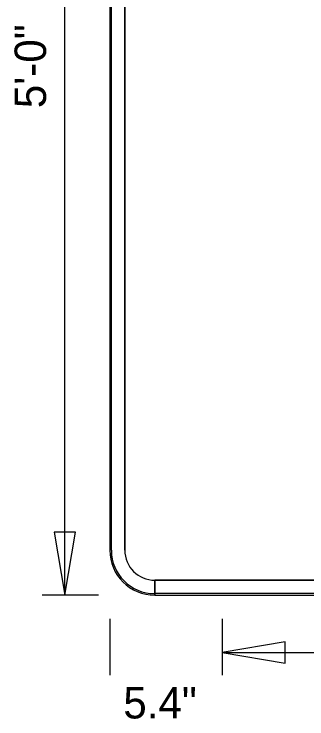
# Model space of a CAD drawing. Extents: x 0 to 770, y 0 to 495.
# Drawn here: x 610.7 to 643.3, y 9.2 to 87.5 of the extents above; entities that cross this region are included whole.
import ezdxf

# ---------------------------------------------------------------- set-up
doc = ezdxf.new("R2010")
doc.units = 0
for name, color, linetype in [('Dimension', 7, 'Continuous'), ('GSBWFill', 7, 'Continuous'), ('GSColorFill', 7, 'Continuous'), ('GSDims', 7, 'Continuous'), ('GSOutline', 7, 'Continuous')]:
    doc.layers.add(name, color=color, linetype=linetype)

msp = doc.modelspace()

# ---------------------------------------------------------------- linework, layer by layer
at = {"layer": 'Dimension'}
for points in [[(616.382, 22.923), (617.571, 29.939), (615.193, 29.939)], [(633.863, 16.542), (640.88, 15.354), (640.88, 17.731)]]:
    msp.add_lwpolyline(points, close=True, dxfattribs=at)
at = {"layer": 'GSBWFill'}
for p, q in [((621.395, 137.635), (621.395, 27.91)), ((623.057, 27.91), (623.057, 137.635)), ((626.382, 22.923), (626.382, 24.585)), ((716.157, 24.585), (626.399, 24.585)), ((626.399, 24.585), (626.399, 22.923)), ((626.399, 22.923), (716.157, 22.923))]:
    msp.add_line(p, q, dxfattribs=at)
for radius in [4.988, 3.325]:
    msp.add_arc((626.382, 27.91), radius, 180, 270, dxfattribs=at)
at = {"layer": 'GSColorFill'}
for p, q in [((621.395, 137.635), (621.395, 27.91)), ((621.395, 137.635), (621.395, 27.91)), ((621.395, 137.635), (621.395, 27.91)), ((621.561, 27.91), (621.561, 137.635)), ((623.057, 27.91), (623.057, 137.635)), ((626.382, 22.923), (626.382, 24.585)), ((716.157, 24.585), (626.399, 24.585)), ((626.399, 24.585), (626.399, 22.923)), ((626.382, 22.923), (626.382, 23.089)), ((626.382, 22.923), (716.157, 22.923)), ((716.157, 23.089), (626.384, 23.089)), ((626.384, 23.089), (626.384, 22.923)), ((626.384, 22.923), (716.157, 22.923)), ((626.399, 22.923), (716.157, 22.923))]:
    msp.add_line(p, q, dxfattribs=at)
for radius in [4.988, 4.988, 4.988, 4.821, 3.325]:
    msp.add_arc((626.382, 27.91), radius, 180, 270, dxfattribs=at)
at = {"layer": 'GSDims'}
for p, q in [((616.382, 22.923), (616.382, 142.623)), ((620.132, 22.923), (613.882, 22.923)), ((621.395, 20.292), (621.395, 14.042)), ((633.863, 20.292), (633.863, 14.042)), ((633.863, 20.292), (633.863, 14.042)), ((633.863, 16.542), (707.097, 16.542))]:
    msp.add_line(p, q, dxfattribs=at)
at = {"layer": 'GSOutline'}
for p, q in [((621.395, 137.635), (621.395, 27.91)), ((623.057, 137.635), (623.057, 27.91)), ((626.382, 24.585), (716.157, 24.585)), ((626.382, 22.923), (716.157, 22.923))]:
    msp.add_line(p, q, dxfattribs=at)
for radius in [4.988, 3.325]:
    msp.add_arc((626.382, 27.91), radius, 180, 270, dxfattribs=at)

# ---------------------------------------------------------------- texts
at = {"layer": 'GSDims'}
msp.add_text('5\'-0"', height=3.5, rotation=90, dxfattribs=at).set_placement((614.302, 77.029))
msp.add_text('5.4"', height=3.5, dxfattribs=at).set_placement((622.89, 9.223))

doc.saveas('drawing.dxf')
